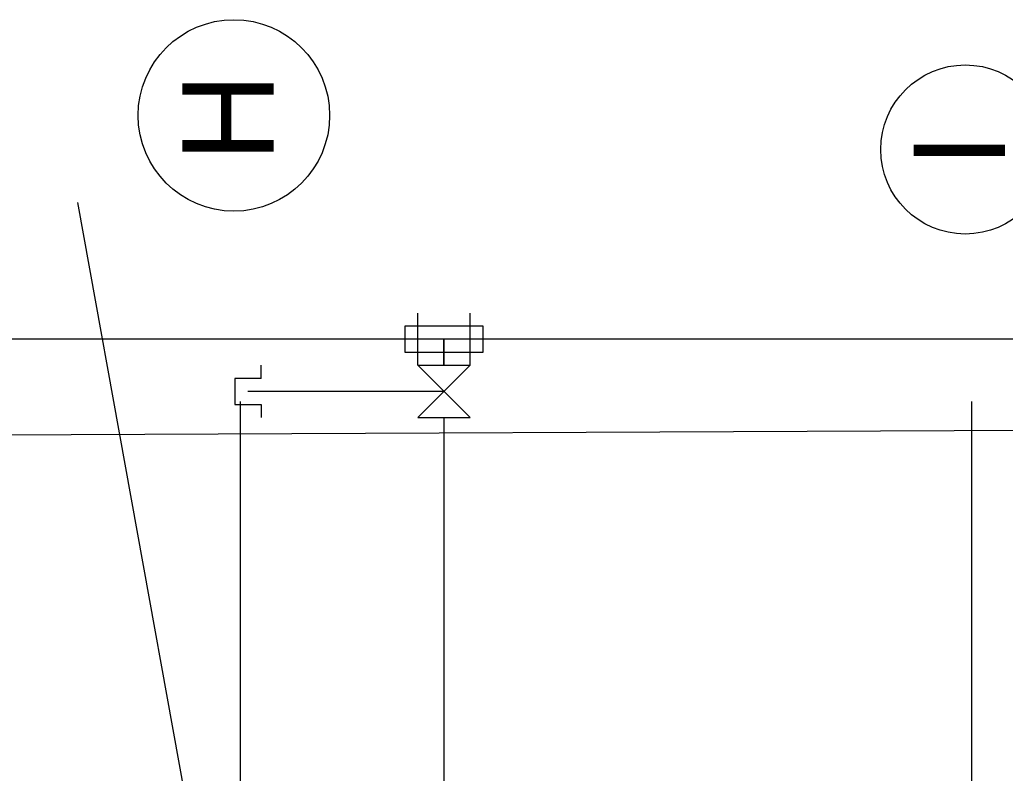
# Model space of a CAD drawing. Extents: x -264031 to -263588, y -1242281 to -1242059.
# Drawn here: x -263871.58 to -263862.14, y -1242086.79 to -1242079.58 of the extents above; entities that cross this region are included whole.
import ezdxf

# ---------------------------------------------------------------- set-up
doc = ezdxf.new("R2010")
doc.units = 0
for name, color, linetype in [('HESCON_OSI_STAVBY_KFA', 7, 'Continuous'), ('KFA_2D_SITUACIA_DSP', 7, 'Continuous'), ('KFA_JESTV_IS_DSP_-_KANAL_SPLASK', 7, 'Continuous')]:
    doc.layers.add(name, color=color, linetype=linetype)

msp = doc.modelspace()

# ---------------------------------------------------------------- linework, layer by layer
at = {"layer": 'HESCON_OSI_STAVBY_KFA'}
for p, q in [((-263869.4678, -1242083.2372), (-263869.4678, -1242083.2372)), ((-263869.4678, -1242083.2372), (-263869.4678, -1242246.7072)), ((-263862.4678, -1242083.2372), (-263862.4678, -1242083.2372)), ((-263862.4678, -1242083.2372), (-263862.4678, -1242246.7072))]:
    msp.add_line(p, q, dxfattribs=at)
for centre, radius in [((-263869.5276, -1242080.498), 0.9163), ((-263862.5276, -1242080.8238), 0.8092)]:
    msp.add_circle(centre, radius, dxfattribs=at)
at = {"layer": 'KFA_2D_SITUACIA_DSP'}
for p, q in [((-263869.8811, -1242087.6334), (-263871.0197, -1242081.332)), ((-263867.7678, -1242082.8898), (-263867.7678, -1242082.3898)), ((-263867.2678, -1242082.8898), (-263867.2678, -1242082.3898)), ((-263867.1428, -1242082.5148), (-263867.8928, -1242082.5148)), ((-263867.8928, -1242082.5148), (-263867.8928, -1242082.7648)), ((-263867.1428, -1242082.7648), (-263867.1428, -1242082.5148)), ((-263788.1428, -1242082.6399), (-263924.1428, -1242082.6399)), ((-263867.5178, -1242082.6398), (-263867.5178, -1242082.8898)), ((-263867.5178, -1242082.8898), (-263867.5178, -1242082.6398)), ((-263867.8928, -1242082.7648), (-263867.1428, -1242082.7648)), ((-263869.2678, -1242083.0148), (-263869.2678, -1242082.8898)), ((-263867.2678, -1242082.8898), (-263867.7679, -1242083.3898)), ((-263867.7678, -1242082.8898), (-263867.2678, -1242082.8898)), ((-263867.2679, -1242083.3898), (-263867.7678, -1242082.8898)), ((-263869.2678, -1242083.0148), (-263869.5178, -1242083.0148)), ((-263869.5178, -1242083.0148), (-263869.5178, -1242083.2648)), ((-263867.5178, -1242083.1398), (-263869.3928, -1242083.1398)), ((-263869.5178, -1242083.2648), (-263869.2678, -1242083.2648)), ((-263869.2678, -1242083.2648), (-263869.2678, -1242083.3898)), ((-263867.7679, -1242083.3898), (-263867.2679, -1242083.3898)), ((-263867.5179, -1242083.3898), (-263867.5178, -1242093.0072))]:
    msp.add_line(p, q, dxfattribs=at)
at = {"layer": 'KFA_JESTV_IS_DSP_-_KANAL_SPLASK'}
msp.add_line((-263853.3422, -1242083.4776), (-263897, -1242083.6658), dxfattribs=at)

# ---------------------------------------------------------------- texts
at = {"layer": 'HESCON_OSI_STAVBY_KFA'}
for s, p in [('H', (-263869.147, -1242080.9394)), ('I', (-263862.147, -1242080.9937))]:
    msp.add_text(s, height=0.875, rotation=90, dxfattribs=at).set_placement(p)

doc.saveas('drawing.dxf')
